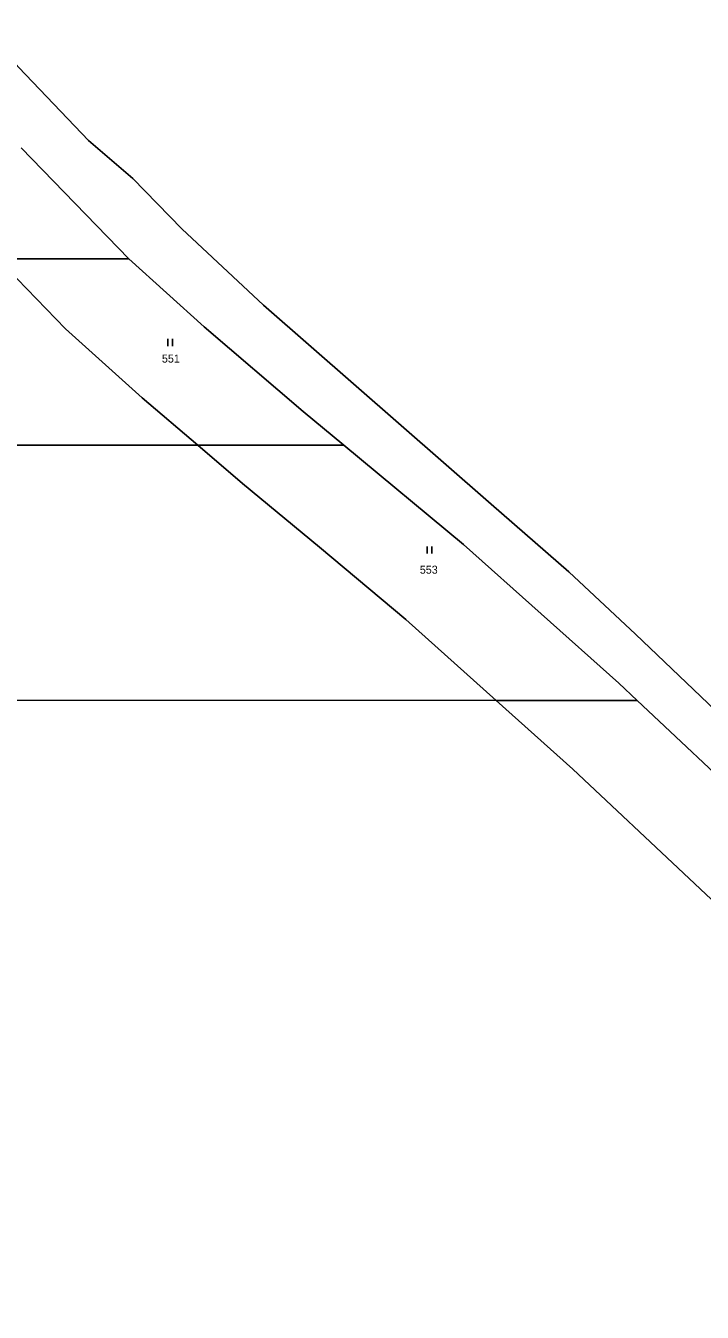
# Model space of a CAD drawing. Extents: x -769392 to -767038, y -1018329 to -1015269.
# Drawn here: x -768424.9 to -768281.2, y -1018061.3 to -1017788.1 of the extents above; entities that cross this region are included whole.
import ezdxf

# ---------------------------------------------------------------- set-up
doc = ezdxf.new("R2010")
doc.units = 0
doc.header["$LTSCALE"] = 0.68
doc.layers.add('1', color=7, linetype='Continuous', lineweight=25)
doc.layers.add('3', color=7, linetype='Continuous', lineweight=25)
doc.layers.add('2', color=7, linetype='Continuous')

msp = doc.modelspace()

# ---------------------------------------------------------------- linework, layer by layer
at = {"layer": '1'}
for p, q in [((-768425.91, -1017814.03), (-768403.04, -1017837.62)), ((-768430.93, -1017837.61), (-768403.04, -1017837.62)), ((-768388.38, -1017877.17), (-768357.35, -1017877.18)), ((-768324.96, -1017931.42), (-768295.04, -1017931.43))]:
    msp.add_line(p, q, dxfattribs=at)
for points in [[(-768556.34, -1017687.33), (-768551.42, -1017689.19), (-768536.34, -1017696.77), (-768524.28, -1017703.42), (-768512.59, -1017711.44), (-768499.71, -1017721.64), (-768477.3, -1017741.63), (-768460.5, -1017758.91), (-768426.34, -1017796.93), (-768411.6, -1017812.49), (-768402.15, -1017820.51), (-768391.72, -1017831.23), (-768374.38, -1017847.47), (-768326.06, -1017889.73), (-768309.54, -1017904.05), (-768295.37, -1017917.29), (-768244.47, -1017965.89)], [(-768388.38, -1017877.17), (-768400.15, -1017867.09), (-768416.47, -1017852.5), (-768430.93, -1017837.61)], [(-768403.04, -1017837.62), (-768386.98, -1017852.04), (-768365.96, -1017870.03), (-768357.35, -1017877.18)], [(-768649.62, -1017877.09), (-768478.31, -1017877.14), (-768388.38, -1017877.17)], [(-768324.96, -1017931.42), (-768344.14, -1017914.2), (-768362.54, -1017898.87), (-768378.85, -1017885.32), (-768388.38, -1017877.17)], [(-768357.35, -1017877.18), (-768331.94, -1017898.28), (-768298.96, -1017927.74), (-768295.04, -1017931.43)], [(-768641.88, -1017931.31), (-768471.54, -1017931.37), (-768324.96, -1017931.42)], [(-767993.47, -1018204.66), (-768074.37, -1018157.5), (-768097.11, -1018141.74), (-768109.87, -1018131.86), (-768133.41, -1018111.1), (-768150.7, -1018094.85), (-768176.29, -1018070.99), (-768208.13, -1018042.05), (-768259.27, -1017992.44), (-768308.71, -1017946.01), (-768324.96, -1017931.42)], [(-768295.04, -1017931.43), (-768245.9, -1017977.57), (-768219.23, -1018002.92), (-768215.4, -1018006.59), (-768194.35, -1018027.55), (-768160.01, -1018058.86), (-768137.3, -1018080), (-768120.16, -1018096.12), (-768097.59, -1018116.08), (-768085.78, -1018125.26), (-768063.62, -1018140.61), (-768006.2, -1018173.9), (-767989.76, -1018183.69), (-767970.68, -1018195.84)]]:
    msp.add_lwpolyline(points, dxfattribs=at)
at = {"layer": '3'}
for p, q in [((-768394.751, -1017856.12), (-768394.751, -1017854.62)), ((-768393.75, -1017856.12), (-768393.75, -1017854.62)), ((-768339.641, -1017900.2), (-768339.641, -1017898.7)), ((-768338.64, -1017900.2), (-768338.64, -1017898.7))]:
    msp.add_line(p, q, dxfattribs=at)

# ---------------------------------------------------------------- texts
at = {"layer": '2'}
for s, p in [('551', (-768395.98, -1017859.635)), ('553', (-768341.2, -1017904.475))]:
    msp.add_text(s, height=1.7, dxfattribs=at).set_placement(p)

doc.saveas('drawing.dxf')
